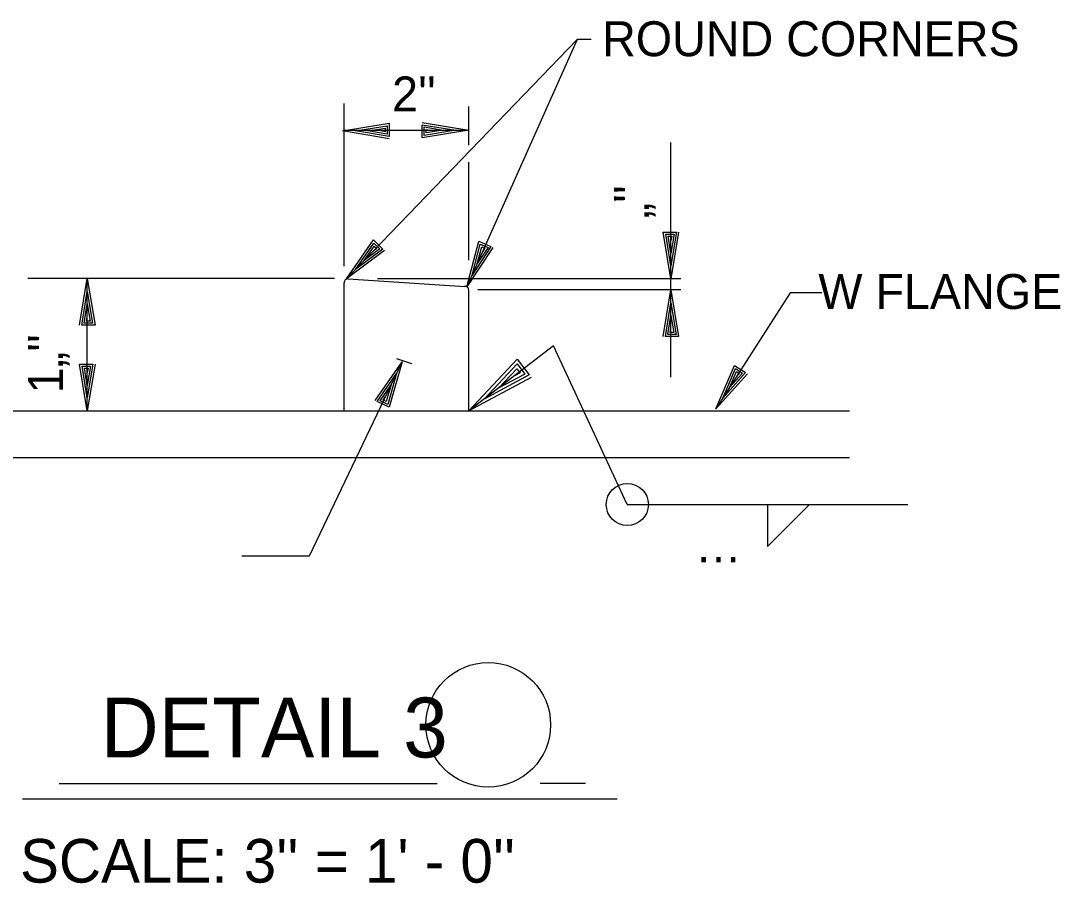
# Model space of a CAD drawing. Extents: x 0 to 53.3, y -2.9 to 37.3.
# Drawn here: x 36.89 to 42.44, y 5.06 to 9.67 of the extents above; entities that cross this region are included whole.
import ezdxf

# ---------------------------------------------------------------- set-up
doc = ezdxf.new("R2010")
doc.units = 0
for name, color, linetype in [('Level 1', 7, 'Continuous'), ('Level 25', 7, 'Continuous'), ('Level 3', 7, 'Continuous'), ('Level 50', 7, 'Continuous')]:
    doc.layers.add(name, color=color, linetype=linetype)

msp = doc.modelspace()

# ---------------------------------------------------------------- linework, layer by layer
at = {"layer": 'Level 25'}
for p, q in [((39.8613, 9.5713), (38.6277, 8.2908)), ((38.6141, 8.3589), (38.6141, 9.2288)), ((39.2808, 9.006), (39.2808, 9.2123)), ((38.6141, 9.086), (39.2808, 9.086)), ((40.3621, 8.2908), (40.3621, 9.0194)), ((39.2808, 8.3912), (39.2808, 8.9152)), ((38.6363, 8.2908), (39.26, 8.2505)), ((40.3621, 8.2313), (40.3621, 8.2908)), ((40.3621, 7.7648), (40.3621, 8.2313)), ((39.7334, 7.9316), (39.2808, 7.5838)), ((40.1287, 7.0833), (39.7334, 7.9316)), ((38.8944, 7.8644), (38.974, 7.8368)), ((39.3633, 7.6472), (39.3633, 7.6472)), ((39.2808, 7.5838), (39.2808, 7.5838)), ((40.1287, 7.0833), (41.6291, 7.0833)), ((40.8787, 7.0833), (40.8787, 6.8583)), ((40.8787, 6.8583), (41.1022, 7.0818))]:
    msp.add_line(p, q, dxfattribs=at)
msp.add_lwpolyline([(39.6152, 7.7625), (39.2808, 7.5838), (39.5396, 7.8608), (39.6042, 7.7768), (39.3633, 7.6472), (39.5391, 7.8352), (39.5806, 7.7813), (39.4426, 7.7081), (39.5386, 7.8096), (39.5557, 7.7874), (39.5251, 7.7715)], dxfattribs=at)
msp.add_circle((40.1288, 7.0832), 0.1125, dxfattribs=at)
at = {"layer": 'Level 3'}
for p, q in [((39.2991, 8.3109), (39.2991, 8.3109)), ((39.2708, 8.2476), (39.2708, 8.2476)), ((38.925, 7.8461), (38.925, 7.8461)), ((38.8951, 7.7835), (38.8951, 7.7835)), ((40.6391, 7.653), (40.6391, 7.653)), ((40.6016, 7.5947), (40.6016, 7.5947)), ((37.0903, 5.5895), (39.1112, 5.5895)), ((39.9055, 5.5895), (39.663, 5.5895)), ((40.0743, 5.5061), (36.895, 5.5061))]:
    msp.add_line(p, q, dxfattribs=at)
for points in [[(39.9355, 9.5713), (39.8613, 9.5713), (39.2708, 8.2476)], [(39.4102, 8.4584), (39.2708, 8.2476), (39.3347, 8.4921), (39.3992, 8.4633), (39.2991, 8.3109), (39.3425, 8.4769), (39.3839, 8.4585), (39.3263, 8.3718), (39.3503, 8.4618), (39.3674, 8.4541), (39.3545, 8.4351)], [(41.1686, 8.2149), (41.0004, 8.2149), (40.6016, 7.5947)], [(38.0667, 6.808), (38.4292, 6.808), (38.925, 7.8461)], [(38.7803, 7.6389), (38.925, 7.8461), (38.8548, 7.6032), (38.7911, 7.6337), (38.8951, 7.7835), (38.8474, 7.6186), (38.8065, 7.6381), (38.8664, 7.7233), (38.84, 7.634), (38.8231, 7.642), (38.8365, 7.6608)], [(40.7713, 7.7821), (40.6016, 7.5947), (40.7017, 7.8268), (40.7611, 7.7886), (40.6391, 7.653), (40.7072, 7.8106), (40.7453, 7.7861), (40.6752, 7.7091), (40.7126, 7.7944), (40.7283, 7.7843), (40.7127, 7.7674)]]:
    msp.add_lwpolyline(points, dxfattribs=at)
msp.add_circle((39.3853, 5.9046), 0.3333, dxfattribs=at)
at = {"layer": 'Level 50'}
for p, q in [((38.6059, 9.0818), (38.6059, 9.0818)), ((38.6752, 9.0818), (38.6752, 9.0818)), ((39.2115, 9.086), (39.2115, 9.086)), ((39.2808, 9.086), (39.2808, 9.086)), ((38.6758, 8.3407), (38.6758, 8.3407)), ((40.3621, 8.3601), (40.3621, 8.3601)), ((38.563, 8.2922), (36.922, 8.2922)), ((37.2408, 7.5838), (37.2408, 8.2922)), ((37.2408, 8.2922), (37.2408, 8.2922)), ((38.6277, 8.2908), (38.6277, 8.2908)), ((40.4147, 8.2908), (38.7925, 8.2908)), ((40.3621, 8.2908), (40.3621, 8.2908)), ((38.6141, 7.5838), (38.6141, 8.27)), ((39.2808, 7.5838), (39.2808, 8.2313)), ((40.4147, 8.2313), (39.3289, 8.2313)), ((40.3621, 8.2313), (40.3621, 8.2313)), ((37.2408, 8.2228), (37.2408, 8.2228)), ((40.3621, 8.162), (40.3621, 8.162)), ((37.2408, 7.6532), (37.2408, 7.6532)), ((36.5905, 7.5838), (41.3166, 7.5838)), ((37.2408, 7.5838), (37.2408, 7.5838)), ((36.5586, 7.3338), (41.3166, 7.3338))]:
    msp.add_line(p, q, dxfattribs=at)
for points in [[(38.8552, 9.0405), (38.6059, 9.0818), (38.8552, 9.1232), (38.8552, 9.0525), (38.6752, 9.0818), (38.8446, 9.1098), (38.8446, 9.0645), (38.7419, 9.0818), (38.8339, 9.0965), (38.8339, 9.0778), (38.8112, 9.0818)], [(39.0315, 9.1273), (39.2808, 9.086), (39.0315, 9.0446), (39.0315, 9.1153), (39.2115, 9.086), (39.0421, 9.058), (39.0421, 9.1033), (39.1448, 9.086), (39.0528, 9.0713), (39.0528, 9.09), (39.0755, 9.086)], [(40.4034, 8.5401), (40.3621, 8.2908), (40.3208, 8.5401), (40.3914, 8.5401), (40.3621, 8.3601), (40.3341, 8.5295), (40.3794, 8.5295), (40.3621, 8.4268), (40.3474, 8.5188), (40.3661, 8.5188), (40.3621, 8.4961)], [(38.8304, 8.4417), (38.6277, 8.2908), (38.7709, 8.4991), (38.8218, 8.45), (38.6758, 8.3407), (38.7731, 8.4821), (38.8058, 8.4506), (38.722, 8.3887), (38.7753, 8.4652), (38.7888, 8.4522), (38.7701, 8.4387)], [(37.1994, 8.0428), (37.2408, 8.2922), (37.2821, 8.0428), (37.2114, 8.0428), (37.2408, 8.2228), (37.2688, 8.0535), (37.2234, 8.0535), (37.2408, 8.1562), (37.2554, 8.0642), (37.2368, 8.0642), (37.2408, 8.0868)], [(40.3208, 7.982), (40.3621, 8.2313), (40.4034, 7.982), (40.3328, 7.982), (40.3621, 8.162), (40.3901, 7.9927), (40.3448, 7.9927), (40.3621, 8.0953), (40.3768, 8.0033), (40.3581, 8.0033), (40.3621, 8.026)], [(37.2821, 7.8332), (37.2408, 7.5838), (37.1994, 7.8332), (37.2701, 7.8332), (37.2408, 7.6532), (37.2128, 7.8225), (37.2581, 7.8225), (37.2408, 7.7198), (37.2261, 7.8118), (37.2448, 7.8118), (37.2408, 7.7892)]]:
    msp.add_lwpolyline(points, dxfattribs=at)
for centre, start, end in [((38.635, 8.27), 86.4207, 180), ((39.26, 8.2298), 0, 93.5793)]:
    msp.add_arc(centre, 0.0208, start, end, dxfattribs=at)

# ---------------------------------------------------------------- texts
at = {"layer": 'Level 1'}
msp.add_text("SCALE: 3'' = 1' - 0''", height=0.233329, dxfattribs=at).set_placement((36.8811, 5.0601))
at = {"layer": 'Level 25'}
for s, height, p in [('ROUND CORNERS', 0.186698, (39.9938, 9.4819)), ("2''", 0.1867, (38.8708, 9.1866)), ('W FLANGE', 0.1867, (41.1507, 8.1294)), ('…', 0.1867, (40.4912, 6.7731))]:
    msp.add_text(s, height=height, dxfattribs=at).set_placement(p)
msp.add_text("1„''", height=0.1867, rotation=90, dxfattribs=at).set_placement((37.111, 7.6778))
at = {"layer": 'Level 3'}
msp.add_text('DETAIL 3', height=0.32, dxfattribs=at).set_placement((37.3136, 5.7298))
at = {"layer": 'Level 50'}
msp.add_text("„'' ", height=0.1867, rotation=90, dxfattribs=at).set_placement((40.2452, 8.6135))

doc.saveas('drawing.dxf')
